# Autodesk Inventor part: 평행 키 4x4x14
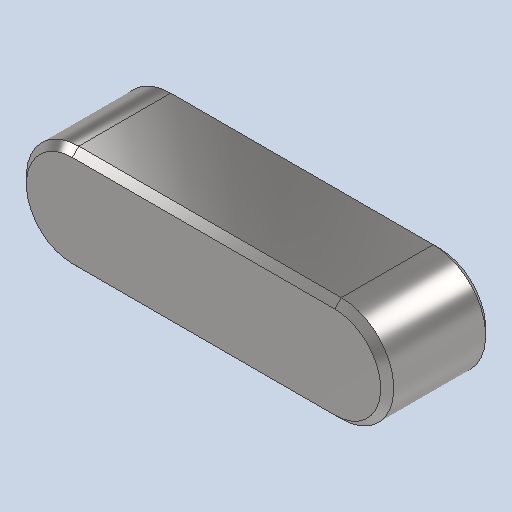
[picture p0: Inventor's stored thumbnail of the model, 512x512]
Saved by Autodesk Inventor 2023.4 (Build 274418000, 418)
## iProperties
Created: 2024-12
Part Number: 평행 키 4x4x14
Material: 강철, 연강
Description: 키 및 해당 키홈
Document SubType Name: Modeling
Designer: EDU
Density: 7.85 g/cm^3
Appearance: 기본값
Author: jhkim
Sending System: Autodesk Inventor 2025
Preprocessor: ST-DEVELOPER v20
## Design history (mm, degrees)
feature "Solid1"
node "솔리드1"
